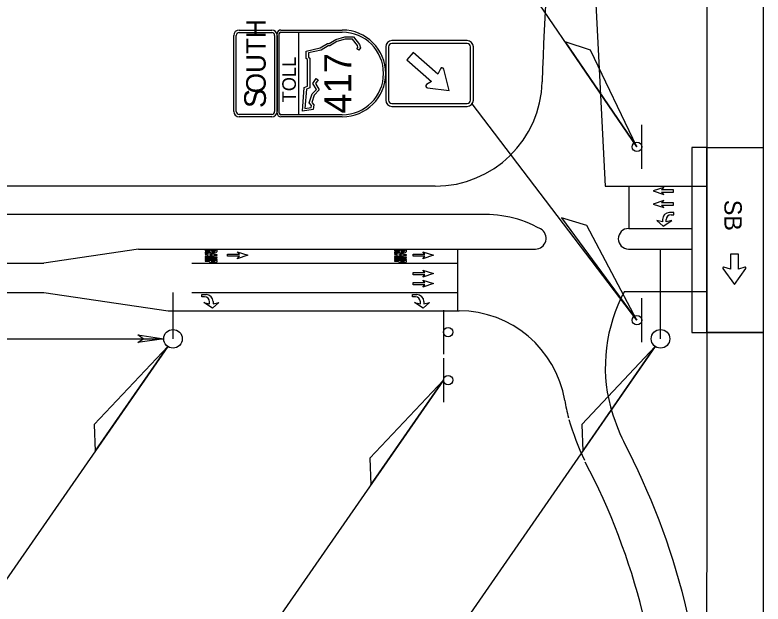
# Model space of a CAD drawing. Extents: x -830008.4 to -829992.7, y 1290284.1 to 1290294.4.
# Drawn here: x -830003.674 to -830000.185, y 1290288.067 to 1290290.815 of the extents above; entities that cross this region are included whole.
import ezdxf

# ---------------------------------------------------------------- set-up
doc = ezdxf.new("R2010")
doc.units = 0
for name, color, linetype in [('1', 7, 'Continuous'), ('DirArrowsPavt', 7, 'Continuous'), ('OOCEA Logo', 7, 'Continuous'), ('PavtMessage', 7, 'Continuous'), ('PlotBorder_dp', 7, 'Continuous'), ('SheetBorder_dp', 7, 'Continuous'), ('SignPanel', 7, 'Continuous')]:
    doc.layers.add(name, color=color, linetype=linetype)

msp = doc.modelspace()

# ---------------------------------------------------------------- linework, layer by layer
at = {"layer": '1'}
for p, q in [((-830000.1852, 1290294.228), (-830000.1852, 1290285.328)), ((-830000.448, 1290293.7828), (-830000.448, 1290288.446)), ((-830000.7731, 1290290.1996), (-830001.6415, 1290291.4727)), ((-830000.9789, 1290291.1282), (-830000.922, 1290290.0166)), ((-830000.7731, 1290289.3913), (-830001.5421, 1290290.4003)), ((-830000.448, 1290290.196), (-830000.1852, 1290290.196)), ((-830001.7147, 1290290.0166), (-830007.4742, 1290290.0166)), ((-830000.922, 1290290.0166), (-830000.448, 1290290.0166)), ((-830000.8113, 1290290.0166), (-830000.8113, 1290289.8188)), ((-830001.5198, 1290289.8838), (-830007.4742, 1290289.8838)), ((-830000.8113, 1290289.8188), (-830000.517, 1290289.8188)), ((-830003.0984, 1290289.7229), (-830003.5393, 1290289.6579)), ((-830003.0984, 1290289.7229), (-830001.247, 1290289.7229)), ((-830001.6094, 1290289.4347), (-830001.6094, 1290289.7229)), ((-830000.8125, 1290289.7229), (-830000.517, 1290289.7229)), ((-830007.4742, 1290289.6579), (-830003.5393, 1290289.6579)), ((-830002.8488, 1290289.6579), (-830001.6094, 1290289.6579)), ((-830007.4742, 1290289.5202), (-830003.5393, 1290289.5202)), ((-830003.5393, 1290289.5202), (-830002.9593, 1290289.4347)), ((-830002.8488, 1290289.5202), (-830001.6094, 1290289.5202)), ((-830000.8318, 1290289.5251), (-830000.448, 1290289.5251)), ((-830002.9593, 1290289.4347), (-830001.6033, 1290289.4347)), ((-830000.448, 1290289.3342), (-830000.1852, 1290289.3342)), ((-830005.2106, 1290289.3045), (-830002.9806, 1290289.3045)), ((-830002.962, 1290289.2687), (-830003.7569, 1290288.1223)), ((-830000.6882, 1290289.2687), (-830001.6523, 1290287.8784)), ((-830001.6762, 1290289.1116), (-830002.665, 1290287.6856)), ((-830000.448, 1290288.446), (-830000.4492, 1290286.7771))]:
    msp.add_line(p, q, dxfattribs=at)
msp.add_lwpolyline([(-830000.448, 1290290.196), (-830000.517, 1290290.196), (-830000.517, 1290289.3342), (-830000.448, 1290289.3342), (-830000.448, 1290290.196)], dxfattribs=at)
msp.add_lwpolyline([(-830000.1852, 1290289.3342), (-830000.448, 1290289.3342), (-830000.448, 1290290.196), (-830000.1852, 1290290.196)], close=True, dxfattribs=at)
for centre, radius, start, end in [((-829989.4075, 1290290.1947), 11.8114, 160.03301, 178.50157), ((-830001.7147, 1290290.5166), 0.5, 270, 358.5016), ((-830001.4861, 1290289.3421), 0.5427, 60.9744, 93.5626), ((-830001.247, 1290289.7729), 0.05, 270, 60.9744), ((-830000.8125, 1290289.7709), 0.0479, 90, 270), ((-830000.1798, 1290289.1727), 0.7411, 151.6081, 194.5356), ((-830001.6033, 1290288.9347), 0.5, 9.4895, 90), ((-830000.1798, 1290289.1727), 0.9433, 189.4895, 194.5356), ((-829999.6893, 1290289.3542), 1.2626, 196.9261, 204.8644), ((-829999.6893, 1290289.3542), 1.4649, 196.9261, 204.8644), ((-830003.8248, 1290287.2554), 3.3762, 0.5435, 27.6732), ((-830003.8248, 1290287.2554), 3.1737, 0.5435, 27.6732)]:
    msp.add_arc(centre, radius, start, end, dxfattribs=at)
at = {"layer": 'DirArrowsPavt'}
for p, q in [((-830000.6481, 1290290.0105), (-830000.6981, 1290289.9938)), ((-830000.6981, 1290289.9938), (-830000.6481, 1290289.9771)), ((-830000.6581, 1290289.9988), (-830000.6481, 1290290.0105)), ((-830000.6031, 1290289.9988), (-830000.6581, 1290289.9988)), ((-830000.6481, 1290289.9771), (-830000.6581, 1290289.9888)), ((-830000.6581, 1290289.9888), (-830000.6031, 1290289.9888)), ((-830000.6031, 1290289.9888), (-830000.6031, 1290289.9988)), ((-830000.6481, 1290289.9498), (-830000.6981, 1290289.9331)), ((-830000.6581, 1290289.9381), (-830000.6481, 1290289.9498)), ((-830000.6981, 1290289.9331), (-830000.6481, 1290289.9165)), ((-830000.6031, 1290289.9381), (-830000.6581, 1290289.9381)), ((-830000.6481, 1290289.9165), (-830000.6581, 1290289.9281)), ((-830000.6581, 1290289.9281), (-830000.6031, 1290289.9281)), ((-830000.6031, 1290289.9281), (-830000.6031, 1290289.9381)), ((-830000.6143, 1290289.8834), (-830000.6006, 1290289.8834)), ((-830002.6279, 1290289.6992), (-830002.6379, 1290289.7108)), ((-830002.6379, 1290289.7108), (-830002.5879, 1290289.6942)), ((-830001.7627, 1290289.6992), (-830001.7727, 1290289.7108)), ((-830001.7727, 1290289.7108), (-830001.7227, 1290289.6942)), ((-830002.6829, 1290289.6892), (-830002.6829, 1290289.6992)), ((-830002.6829, 1290289.6992), (-830002.6279, 1290289.6992)), ((-830002.6279, 1290289.6892), (-830002.6829, 1290289.6892)), ((-830002.5879, 1290289.6942), (-830002.6379, 1290289.6775)), ((-830002.6379, 1290289.6775), (-830002.6279, 1290289.6892)), ((-830001.8177, 1290289.6892), (-830001.8177, 1290289.6992)), ((-830001.8177, 1290289.6992), (-830001.7627, 1290289.6992)), ((-830001.7627, 1290289.6892), (-830001.8177, 1290289.6892)), ((-830001.7227, 1290289.6942), (-830001.7727, 1290289.6775)), ((-830001.7727, 1290289.6775), (-830001.7627, 1290289.6892)), ((-830001.8177, 1290289.6035), (-830001.8177, 1290289.6135)), ((-830001.8177, 1290289.6135), (-830001.7627, 1290289.6135)), ((-830001.7627, 1290289.6035), (-830001.8177, 1290289.6035)), ((-830001.7627, 1290289.6135), (-830001.7727, 1290289.6252)), ((-830001.7727, 1290289.6252), (-830001.7227, 1290289.6085)), ((-830001.7227, 1290289.6085), (-830001.7727, 1290289.5918)), ((-830001.7727, 1290289.5918), (-830001.7627, 1290289.6035)), ((-830001.8177, 1290289.5569), (-830001.8177, 1290289.5669)), ((-830001.8177, 1290289.5669), (-830001.7627, 1290289.5669)), ((-830001.7627, 1290289.5669), (-830001.7727, 1290289.5786)), ((-830001.7727, 1290289.5786), (-830001.7227, 1290289.5619)), ((-830001.7627, 1290289.5569), (-830001.8177, 1290289.5569)), ((-830001.7227, 1290289.5619), (-830001.7727, 1290289.5453)), ((-830001.7727, 1290289.5453), (-830001.7627, 1290289.5569)), ((-830002.7898, 1290289.5005), (-830002.8035, 1290289.5005)), ((-830001.8065, 1290289.5005), (-830001.8202, 1290289.5005))]:
    msp.add_line(p, q, dxfattribs=at)
for points in [[(-830000.6006, 1290289.8834), (-830000.6006, 1290289.8934), (-830000.6211, 1290289.8934)], [(-830000.6539, 1290289.8605), (-830000.6539, 1290289.85), (-830000.6806, 1290289.8567), (-830000.6506, 1290289.83), (-830000.6106, 1290289.8567), (-830000.6373, 1290289.85), (-830000.6373, 1290289.8604)], [(-830002.8035, 1290289.5005), (-830002.8035, 1290289.5105), (-830002.783, 1290289.5105)], [(-830001.8202, 1290289.5005), (-830001.8202, 1290289.5105), (-830001.7997, 1290289.5105)], [(-830002.7502, 1290289.4777), (-830002.7502, 1290289.4672), (-830002.7235, 1290289.4739), (-830002.7535, 1290289.4472), (-830002.7935, 1290289.4739), (-830002.7669, 1290289.4672), (-830002.7669, 1290289.4776)], [(-830001.7668, 1290289.4777), (-830001.7668, 1290289.4672), (-830001.7402, 1290289.4739), (-830001.7702, 1290289.4472), (-830001.8102, 1290289.4739), (-830001.7835, 1290289.4672), (-830001.7835, 1290289.4776)]]:
    msp.add_lwpolyline(points, dxfattribs=at)
for centre, radius, start, end in [((-830000.6211, 1290289.8605), 0.0328, 90, 180), ((-830000.6143, 1290289.8604), 0.023, 90, 180), ((-830002.7898, 1290289.4776), 0.023, 0, 90), ((-830002.783, 1290289.4777), 0.0328, 0, 90), ((-830001.8065, 1290289.4776), 0.023, 0, 90), ((-830001.7997, 1290289.4777), 0.0328, 0, 90)]:
    msp.add_arc(centre, radius, start, end, dxfattribs=at)
at = {"layer": 'OOCEA Logo'}
for p, q in [((-830000.6635, 1290289.3045), (-830000.6635, 1290289.7229)), ((-830002.9372, 1290289.3045), (-830002.9372, 1290289.5202))]:
    msp.add_line(p, q, dxfattribs=at)
for centre in [(-830002.9372, 1290289.3045), (-830000.6635, 1290289.3045), (-830000.6635, 1290289.3045)]:
    msp.add_circle(centre, 0.0434, dxfattribs=at)
at = {"layer": 'PavtMessage'}
for p, q in [((-830002.7876, 1290289.7022), (-830002.7876, 1290289.6999)), ((-830002.731, 1290289.6964), (-830002.7876, 1290289.7022)), ((-830002.7876, 1290289.6999), (-830002.7758, 1290289.6982)), ((-830002.7876, 1290289.6881), (-830002.731, 1290289.694)), ((-830002.7758, 1290289.6921), (-830002.7876, 1290289.6905)), ((-830002.7876, 1290289.6905), (-830002.7876, 1290289.6881)), ((-830002.731, 1290289.6854), (-830002.7876, 1290289.6854)), ((-830002.7876, 1290289.6854), (-830002.7876, 1290289.683)), ((-830002.7876, 1290289.683), (-830002.7593, 1290289.683)), ((-830002.7593, 1290289.683), (-830002.7876, 1290289.6807)), ((-830002.7876, 1290289.6807), (-830002.7876, 1290289.6783)), ((-830002.7876, 1290289.6783), (-830002.7593, 1290289.676)), ((-830002.7593, 1290289.676), (-830002.7876, 1290289.676)), ((-830002.7876, 1290289.676), (-830002.7876, 1290289.6736)), ((-830002.7876, 1290289.6736), (-830002.731, 1290289.6736)), ((-830002.7758, 1290289.6982), (-830002.7758, 1290289.6921)), ((-830002.7734, 1290289.6795), (-830002.731, 1290289.683)), ((-830002.731, 1290289.676), (-830002.7734, 1290289.6795)), ((-830002.764, 1290289.6938), (-830002.764, 1290289.6965)), ((-830002.764, 1290289.6965), (-830002.7546, 1290289.6952)), ((-830002.7546, 1290289.6952), (-830002.764, 1290289.6938)), ((-830002.731, 1290289.694), (-830002.731, 1290289.6964)), ((-830002.731, 1290289.683), (-830002.731, 1290289.6854)), ((-830002.731, 1290289.6736), (-830002.731, 1290289.676)), ((-830001.9045, 1290289.7022), (-830001.9045, 1290289.6999)), ((-830001.8478, 1290289.6964), (-830001.9045, 1290289.7022)), ((-830001.9045, 1290289.6999), (-830001.8927, 1290289.6982)), ((-830001.9045, 1290289.6881), (-830001.8478, 1290289.694)), ((-830001.8927, 1290289.6921), (-830001.9045, 1290289.6905)), ((-830001.9045, 1290289.6905), (-830001.9045, 1290289.6881)), ((-830001.8478, 1290289.6854), (-830001.9045, 1290289.6854)), ((-830001.9045, 1290289.6854), (-830001.9045, 1290289.683)), ((-830001.9045, 1290289.683), (-830001.8762, 1290289.683)), ((-830001.8762, 1290289.683), (-830001.9045, 1290289.6807)), ((-830001.9045, 1290289.6807), (-830001.9045, 1290289.6783)), ((-830001.9045, 1290289.6783), (-830001.8762, 1290289.676)), ((-830001.8762, 1290289.676), (-830001.9045, 1290289.676)), ((-830001.9045, 1290289.676), (-830001.9045, 1290289.6736)), ((-830001.9045, 1290289.6736), (-830001.8478, 1290289.6736)), ((-830001.8927, 1290289.6982), (-830001.8927, 1290289.6921)), ((-830001.8903, 1290289.6795), (-830001.8478, 1290289.683)), ((-830001.8478, 1290289.676), (-830001.8903, 1290289.6795)), ((-830001.8809, 1290289.6938), (-830001.8809, 1290289.6965)), ((-830001.8809, 1290289.6965), (-830001.8714, 1290289.6952)), ((-830001.8714, 1290289.6952), (-830001.8809, 1290289.6938)), ((-830001.8478, 1290289.694), (-830001.8478, 1290289.6964)), ((-830001.8478, 1290289.683), (-830001.8478, 1290289.6854)), ((-830001.8478, 1290289.6736), (-830001.8478, 1290289.676)), ((-830002.731, 1290289.6693), (-830002.7876, 1290289.6693)), ((-830002.7876, 1290289.6693), (-830002.7876, 1290289.6669)), ((-830002.7876, 1290289.6669), (-830002.7687, 1290289.6669)), ((-830002.7593, 1290289.6669), (-830002.7404, 1290289.6669)), ((-830002.7569, 1290289.6598), (-830002.7428, 1290289.6598)), ((-830002.7451, 1290289.6622), (-830002.7545, 1290289.6622)), ((-830002.731, 1290289.6669), (-830002.731, 1290289.6693)), ((-830001.8478, 1290289.6693), (-830001.9045, 1290289.6693)), ((-830001.9045, 1290289.6693), (-830001.9045, 1290289.6669)), ((-830001.9045, 1290289.6669), (-830001.8856, 1290289.6669)), ((-830001.8761, 1290289.6669), (-830001.8573, 1290289.6669)), ((-830001.8738, 1290289.6598), (-830001.8596, 1290289.6598)), ((-830001.862, 1290289.6622), (-830001.8714, 1290289.6622)), ((-830001.8478, 1290289.6669), (-830001.8478, 1290289.6693))]:
    msp.add_line(p, q, dxfattribs=at)
for points in [[(-830002.731, 1290289.7146), (-830002.731, 1290289.7178), (-830002.7377, 1290289.7179), (-830002.7603, 1290289.7179), (-830002.7867, 1290289.7179), (-830002.7876, 1290289.7178), (-830002.7876, 1290289.7154), (-830002.7648, 1290289.7154), (-830002.7648, 1290289.7119)], [(-830002.7648, 1290289.7119), (-830002.7876, 1290289.7084), (-830002.7876, 1290289.706), (-830002.7647, 1290289.7092)], [(-830002.7597, 1290289.706), (-830002.7401, 1290289.706)], [(-830002.757, 1290289.7127), (-830002.7569, 1290289.7154), (-830002.7404, 1290289.7154), (-830002.7404, 1290289.7132)], [(-830001.8478, 1290289.7146), (-830001.8478, 1290289.7178), (-830001.8545, 1290289.7179), (-830001.8772, 1290289.7179), (-830001.9036, 1290289.7179), (-830001.9045, 1290289.7178), (-830001.9045, 1290289.7154), (-830001.8817, 1290289.7154), (-830001.8817, 1290289.7119)], [(-830001.8817, 1290289.7119), (-830001.9045, 1290289.7084), (-830001.9045, 1290289.706), (-830001.8816, 1290289.7092)], [(-830001.8766, 1290289.706), (-830001.857, 1290289.706)], [(-830001.8739, 1290289.7127), (-830001.8738, 1290289.7154), (-830001.8573, 1290289.7154), (-830001.8573, 1290289.7132)]]:
    msp.add_lwpolyline(points, dxfattribs=at)
for centre, radius, start, end in [((-830002.7591, 1290289.7126), 0.00659, 210.876, 264.4327), ((-830002.749, 1290289.7223), 0.0125, 229.8768, 313.4926), ((-830002.7404, 1290289.7154), 0.00948, 271.9759, 354.6981), ((-830001.876, 1290289.7126), 0.00659, 210.876, 264.4327), ((-830001.8658, 1290289.7223), 0.0125, 229.8768, 313.4926), ((-830001.8573, 1290289.7154), 0.00948, 271.9759, 354.6981), ((-830002.7545, 1290289.6669), 0.00472, 180, 270), ((-830002.7451, 1290289.6669), 0.00472, 270, 360), ((-830001.8714, 1290289.6669), 0.00472, 180, 270), ((-830001.862, 1290289.6669), 0.00472, 270, 360)]:
    msp.add_arc(centre, radius, start, end, dxfattribs=at)
for centre, start_param, end_param in [((-830002.7569, 1290289.6669), 3.141593, 4.712389), ((-830002.7428, 1290289.6669), 4.71335, 6.283185), ((-830001.8738, 1290289.6669), 3.141593, 4.712389), ((-830001.8596, 1290289.6669), 4.71335, 6.283185)]:
    msp.add_ellipse(centre, major_axis=(0.0118, 0), ratio=0.6, start_param=start_param, end_param=end_param, dxfattribs=at)
at = {"layer": 'PlotBorder_dp'}
for p, q in [((-830000.7511, 1290290.0967), (-830000.7511, 1290290.3025)), ((-830000.7511, 1290289.2884), (-830000.7511, 1290289.4942)), ((-830001.6762, 1290289.4386), (-830001.6762, 1290289.2328)), ((-830001.6762, 1290289.2145), (-830001.6762, 1290289.0087))]:
    msp.add_line(p, q, dxfattribs=at)
for centre in [(-830000.7731, 1290290.1996), (-830000.7731, 1290289.3913), (-830001.6542, 1290289.3357), (-830001.6542, 1290289.1116)]:
    msp.add_circle(centre, 0.0221, dxfattribs=at)
at = {"layer": 'SheetBorder_dp'}
for p, q in [((-830002.2504, 1290290.6612), (-830002.217, 1290290.682)), ((-830002.217, 1290290.682), (-830002.2086, 1290290.682)), ((-830002.2086, 1290290.682), (-830002.1776, 1290290.7008)), ((-830002.1734, 1290290.691), (-830002.2056, 1290290.6714)), ((-830002.1776, 1290290.7008), (-830002.1352, 1290290.7124)), ((-830002.1338, 1290290.7018), (-830002.1734, 1290290.691)), ((-830002.1352, 1290290.7124), (-830002.0956, 1290290.7124)), ((-830002.1006, 1290290.7018), (-830002.1338, 1290290.7018)), ((-830002.077, 1290290.673), (-830002.1006, 1290290.7018)), ((-830002.0956, 1290290.7124), (-830002.0673, 1290290.6778)), ((-830002.3162, 1290290.6459), (-830002.2504, 1290290.6612)), ((-830002.2464, 1290290.6513), (-830002.3056, 1290290.6375)), ((-830002.214, 1290290.6714), (-830002.2464, 1290290.6513)), ((-830002.2056, 1290290.6714), (-830002.214, 1290290.6714)), ((-830002.0793, 1290290.6571), (-830002.0747, 1290290.6636)), ((-830002.0706, 1290290.651), (-830002.0793, 1290290.6571)), ((-830002.0747, 1290290.6636), (-830002.077, 1290290.673)), ((-830002.0634, 1290290.6614), (-830002.0706, 1290290.651)), ((-830002.0673, 1290290.6778), (-830002.0634, 1290290.6614)), ((-830002.3162, 1290290.6122), (-830002.3162, 1290290.6459)), ((-830002.3092, 1290290.6074), (-830002.3162, 1290290.6122)), ((-830002.3056, 1290290.6375), (-830002.3056, 1290290.6178)), ((-830002.3056, 1290290.6178), (-830002.2987, 1290290.613)), ((-830002.2987, 1290290.613), (-830002.2987, 1290290.4748)), ((-830001.8164, 1290290.6392), (-830001.8459, 1290290.6056)), ((-830001.7017, 1290290.5387), (-830001.8164, 1290290.6392)), ((-830002.3092, 1290290.482), (-830002.3092, 1290290.6074)), ((-830001.8459, 1290290.6056), (-830001.7312, 1290290.505)), ((-830001.6903, 1290290.5636), (-830001.7017, 1290290.5387)), ((-830001.649, 1290290.4627), (-830001.6743, 1290290.5622)), ((-830002.2851, 1290290.4956), (-830002.2697, 1290290.5184)), ((-830002.2609, 1290290.5125), (-830002.2727, 1290290.4952)), ((-830002.2697, 1290290.5184), (-830002.2609, 1290290.5125)), ((-830002.3334, 1290290.3665), (-830002.3249, 1290290.4759)), ((-830002.3249, 1290290.4759), (-830002.3092, 1290290.482)), ((-830002.2987, 1290290.4748), (-830002.3149, 1290290.4684)), ((-830002.2686, 1290290.4675), (-830002.2851, 1290290.4956)), ((-830002.2727, 1290290.4952), (-830002.2556, 1290290.4661)), ((-830001.7312, 1290290.505), (-830001.7545, 1290290.4904)), ((-830001.7509, 1290290.4748), (-830001.649, 1290290.4627)), ((-830002.3149, 1290290.4684), (-830002.3218, 1290290.379)), ((-830002.3015, 1290290.4046), (-830002.2878, 1290290.4468)), ((-830002.2785, 1290290.4413), (-830002.2898, 1290290.4067)), ((-830002.2878, 1290290.4468), (-830002.2686, 1290290.4675)), ((-830002.2556, 1290290.4661), (-830002.2785, 1290290.4413)), ((-830002.2918, 1290290.3922), (-830002.3015, 1290290.4046)), ((-830002.2898, 1290290.4067), (-830002.2808, 1290290.3952)), ((-830002.2833, 1290290.3743), (-830002.3334, 1290290.3665)), ((-830002.3218, 1290290.379), (-830002.2928, 1290290.3835)), ((-830002.2928, 1290290.3835), (-830002.2918, 1290290.3922)), ((-830002.2808, 1290290.3952), (-830002.2833, 1290290.3743)), ((-830000.3721, 1290289.6321), (-830000.3721, 1290289.6321)), ((-830000.319, 1290289.5574), (-830000.2659, 1290289.6321))]:
    msp.add_line(p, q, dxfattribs=at)
for points in [[(-830002.654, 1290290.3648), (-830002.654, 1290290.7192)], [(-830002.6424, 1290290.3648), (-830002.6424, 1290290.7192)], [(-830002.6287, 1290290.7445), (-830002.4768, 1290290.7445)], [(-830002.6287, 1290290.7329), (-830002.4768, 1290290.7329)], [(-830002.4631, 1290290.7192), (-830002.4631, 1290290.3648)], [(-830002.4515, 1290290.3564), (-830002.4515, 1290290.7276)], [(-830002.4515, 1290290.7192), (-830002.4515, 1290290.3648)], [(-830002.4414, 1290290.3564), (-830002.4414, 1290290.7276)], [(-830002.4346, 1290290.7445), (-830002.1477, 1290290.7445)], [(-830002.4346, 1290290.7344), (-830002.1477, 1290290.7344)], [(-830002.3502, 1290290.3496), (-830002.3502, 1290290.7344)], [(-830001.5655, 1290290.6954), (-830001.916, 1290290.6954)], [(-830001.5655, 1290290.682), (-830001.916, 1290290.682)], [(-830001.9452, 1290290.6662), (-830001.9452, 1290290.4178)], [(-830001.9319, 1290290.6662), (-830001.9319, 1290290.4178)], [(-830001.5496, 1290290.4178), (-830001.5496, 1290290.6662)], [(-830001.5362, 1290290.4178), (-830001.5362, 1290290.6662)], [(-830001.916, 1290290.402), (-830001.5655, 1290290.402)], [(-830001.916, 1290290.3886), (-830001.5655, 1290290.3886)], [(-830002.4768, 1290290.3511), (-830002.6287, 1290290.3511)], [(-830002.4768, 1290290.3395), (-830002.6287, 1290290.3395)], [(-830002.1477, 1290290.3496), (-830002.4346, 1290290.3496)], [(-830002.1477, 1290290.3395), (-830002.4346, 1290290.3395)], [(-830000.2694, 1290289.6379), (-830000.3003, 1290289.6286), (-830000.3003, 1290289.6998), (-830000.3377, 1290289.6998), (-830000.3377, 1290289.6286), (-830000.3686, 1290289.6379)], [(-830000.3721, 1290289.6321), (-830000.319, 1290289.5574), (-830000.319, 1290289.5574)]]:
    msp.add_lwpolyline(points, dxfattribs=at)
for centre, radius, start, end in [((-830002.6287, 1290290.7192), 0.0253, 90, 180), ((-830002.6287, 1290290.7192), 0.0137, 90, 180), ((-830002.4768, 1290290.7192), 0.0253, 0, 90), ((-830002.4768, 1290290.7192), 0.0137, 0, 90), ((-830002.4346, 1290290.7276), 0.0169, 90, 180), ((-830002.4346, 1290290.7276), 0.00675, 90, 180), ((-830002.1477, 1290290.542), 0.2025, 270, 90), ((-830002.1477, 1290290.542), 0.1924, 270, 90), ((-830001.916, 1290290.6662), 0.0292, 90, 180), ((-830001.916, 1290290.6662), 0.0158, 90, 179.9456), ((-830001.5655, 1290290.6662), 0.0292, 360, 90), ((-830001.5655, 1290290.6662), 0.0158, 0.0544, 90), ((-830001.6825, 1290290.5601), 0.00852, 14.2549, 155.3873), ((-830001.7499, 1290290.4832), 0.00852, 122.0987, 263.2311), ((-830001.916, 1290290.4178), 0.0292, 180, 270), ((-830001.916, 1290290.4178), 0.0158, 180, 270), ((-830001.5655, 1290290.4178), 0.0292, 270, 0), ((-830001.5655, 1290290.4178), 0.0158, 270, 0), ((-830002.6287, 1290290.3648), 0.0253, 180, 270), ((-830002.6287, 1290290.3648), 0.0137, 180, 270), ((-830002.4768, 1290290.3648), 0.0253, 270, 360), ((-830002.4768, 1290290.3648), 0.0137, 270, 360), ((-830002.4346, 1290290.3564), 0.0169, 180, 270), ((-830002.4346, 1290290.3564), 0.00675, 180, 270), ((-830000.3692, 1290289.6345), 0.00355, 72.8195, 215.3924), ((-830000.2688, 1290289.6345), 0.00355, 324.6076, 107.1805)]:
    msp.add_arc(centre, radius, start, end, dxfattribs=at)
at = {"layer": 'SignPanel'}
for p, q in [((-830000.9905, 1290290.6499), (-830001.1075, 1290290.6898)), ((-830001.1075, 1290290.6898), (-830000.7731, 1290290.1996)), ((-830000.7731, 1290290.1996), (-830000.9905, 1290290.6499)), ((-830001.0063, 1290289.8336), (-830001.1247, 1290289.8693)), ((-830001.1247, 1290289.8693), (-830000.7731, 1290289.3913)), ((-830000.7731, 1290289.3913), (-830001.0063, 1290289.8336)), ((-830003.0766, 1290289.3045), (-830003.1006, 1290289.3225)), ((-830003.1006, 1290289.3225), (-830002.9806, 1290289.3045)), ((-830002.9806, 1290289.3045), (-830003.1006, 1290289.2865)), ((-830003.1006, 1290289.2865), (-830003.0766, 1290289.3045)), ((-830002.962, 1290289.2687), (-830003.3047, 1290288.9047)), ((-830003.3001, 1290288.7811), (-830002.962, 1290289.2687)), ((-830000.6882, 1290289.2687), (-830001.0309, 1290288.9047)), ((-830001.0263, 1290288.7811), (-830000.6882, 1290289.2687)), ((-830001.6762, 1290289.1116), (-830002.0189, 1290288.7475)), ((-830002.0143, 1290288.624), (-830001.6762, 1290289.1116)), ((-830003.3047, 1290288.9047), (-830003.3001, 1290288.7811)), ((-830001.0309, 1290288.9047), (-830001.0263, 1290288.7811)), ((-830002.0189, 1290288.7475), (-830002.0143, 1290288.624))]:
    msp.add_line(p, q, dxfattribs=at)

# ---------------------------------------------------------------- texts
at = {"layer": '1'}
msp.add_text('SB', height=0.081, rotation=270, dxfattribs=at).set_placement((-830000.3654, 1290289.9525))
at = {"layer": 'SheetBorder_dp'}
for s, height, p in [('OUTH', 0.09113, (-830002.5049, 1290290.4496)), ('TOLL', 0.06328, (-830002.3642, 1290290.4076)), ('417', 0.12656, (-830002.1055, 1290290.3546)), ('S', 0.1013, (-830002.5038, 1290290.3804))]:
    msp.add_text(s, height=height, rotation=90, dxfattribs=at).set_placement(p)

doc.saveas('drawing.dxf')
